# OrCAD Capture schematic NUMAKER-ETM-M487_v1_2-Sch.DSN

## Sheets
1 PAGE04 USB: size B; title: USB; rev: v1.2; note: NuMaker-ETM-M487
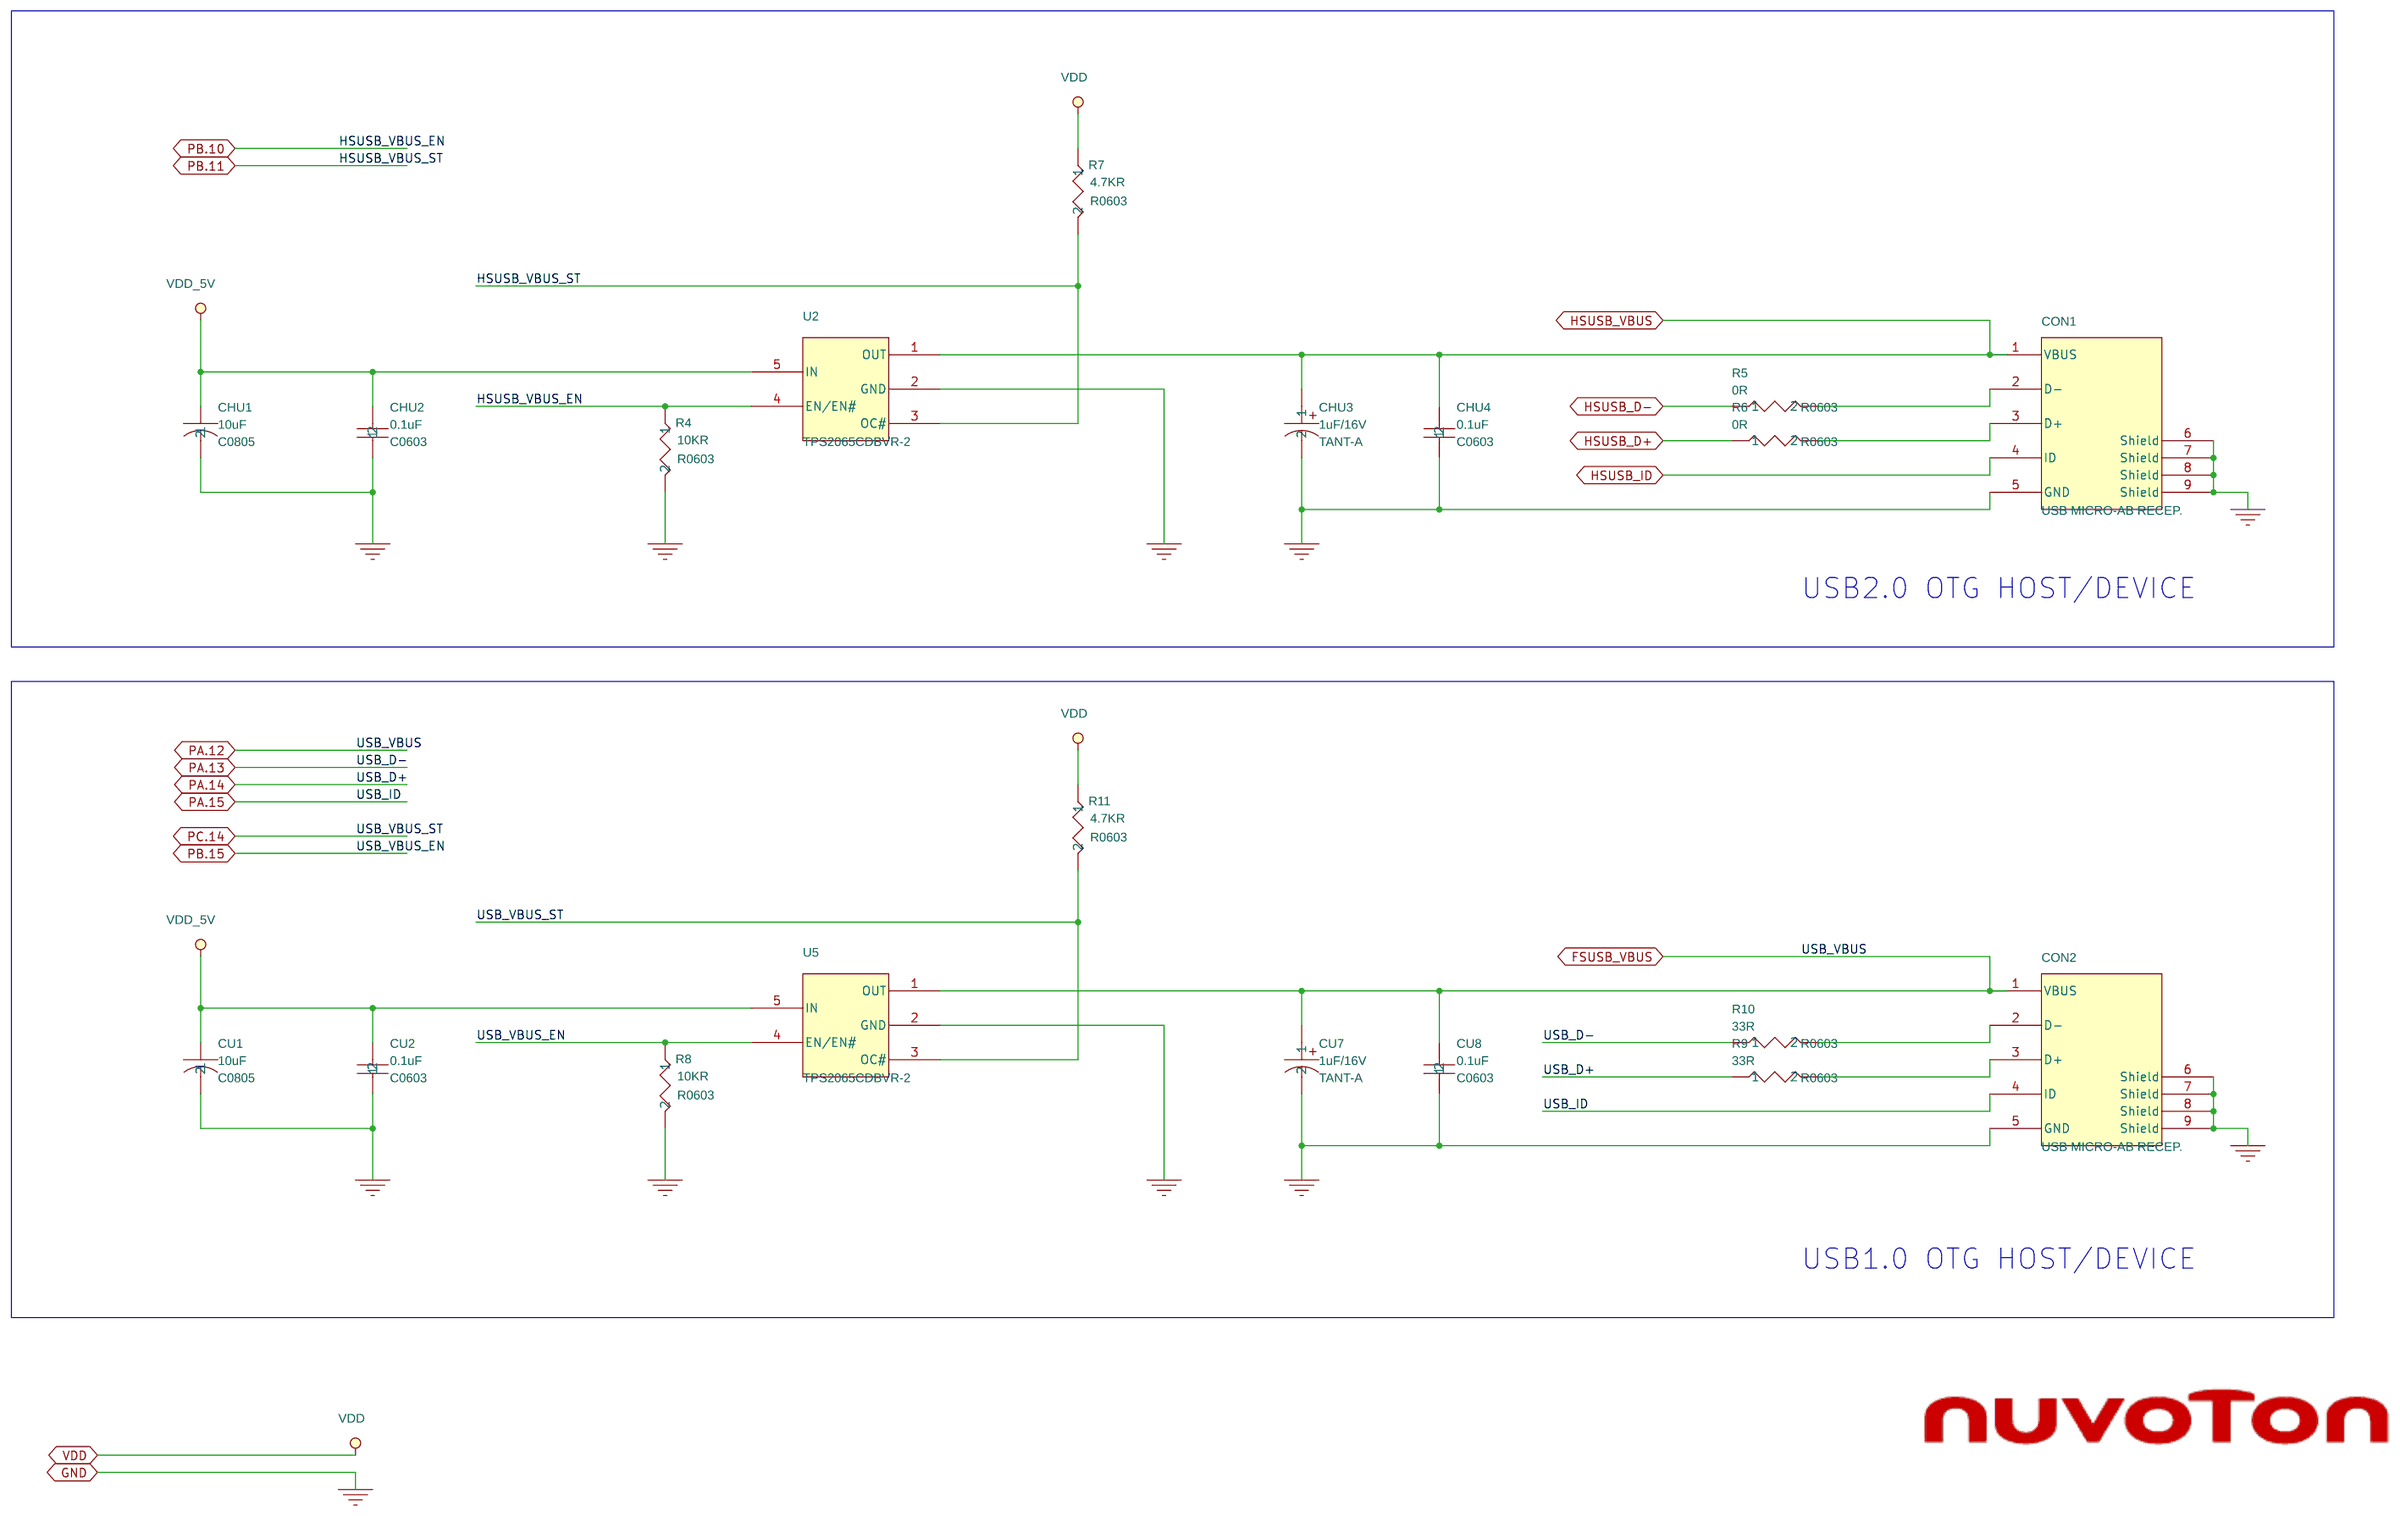
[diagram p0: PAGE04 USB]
2 PAGE01 Nu-Link-Me V3.0: size B; title: Nu-Link-Me v3.0
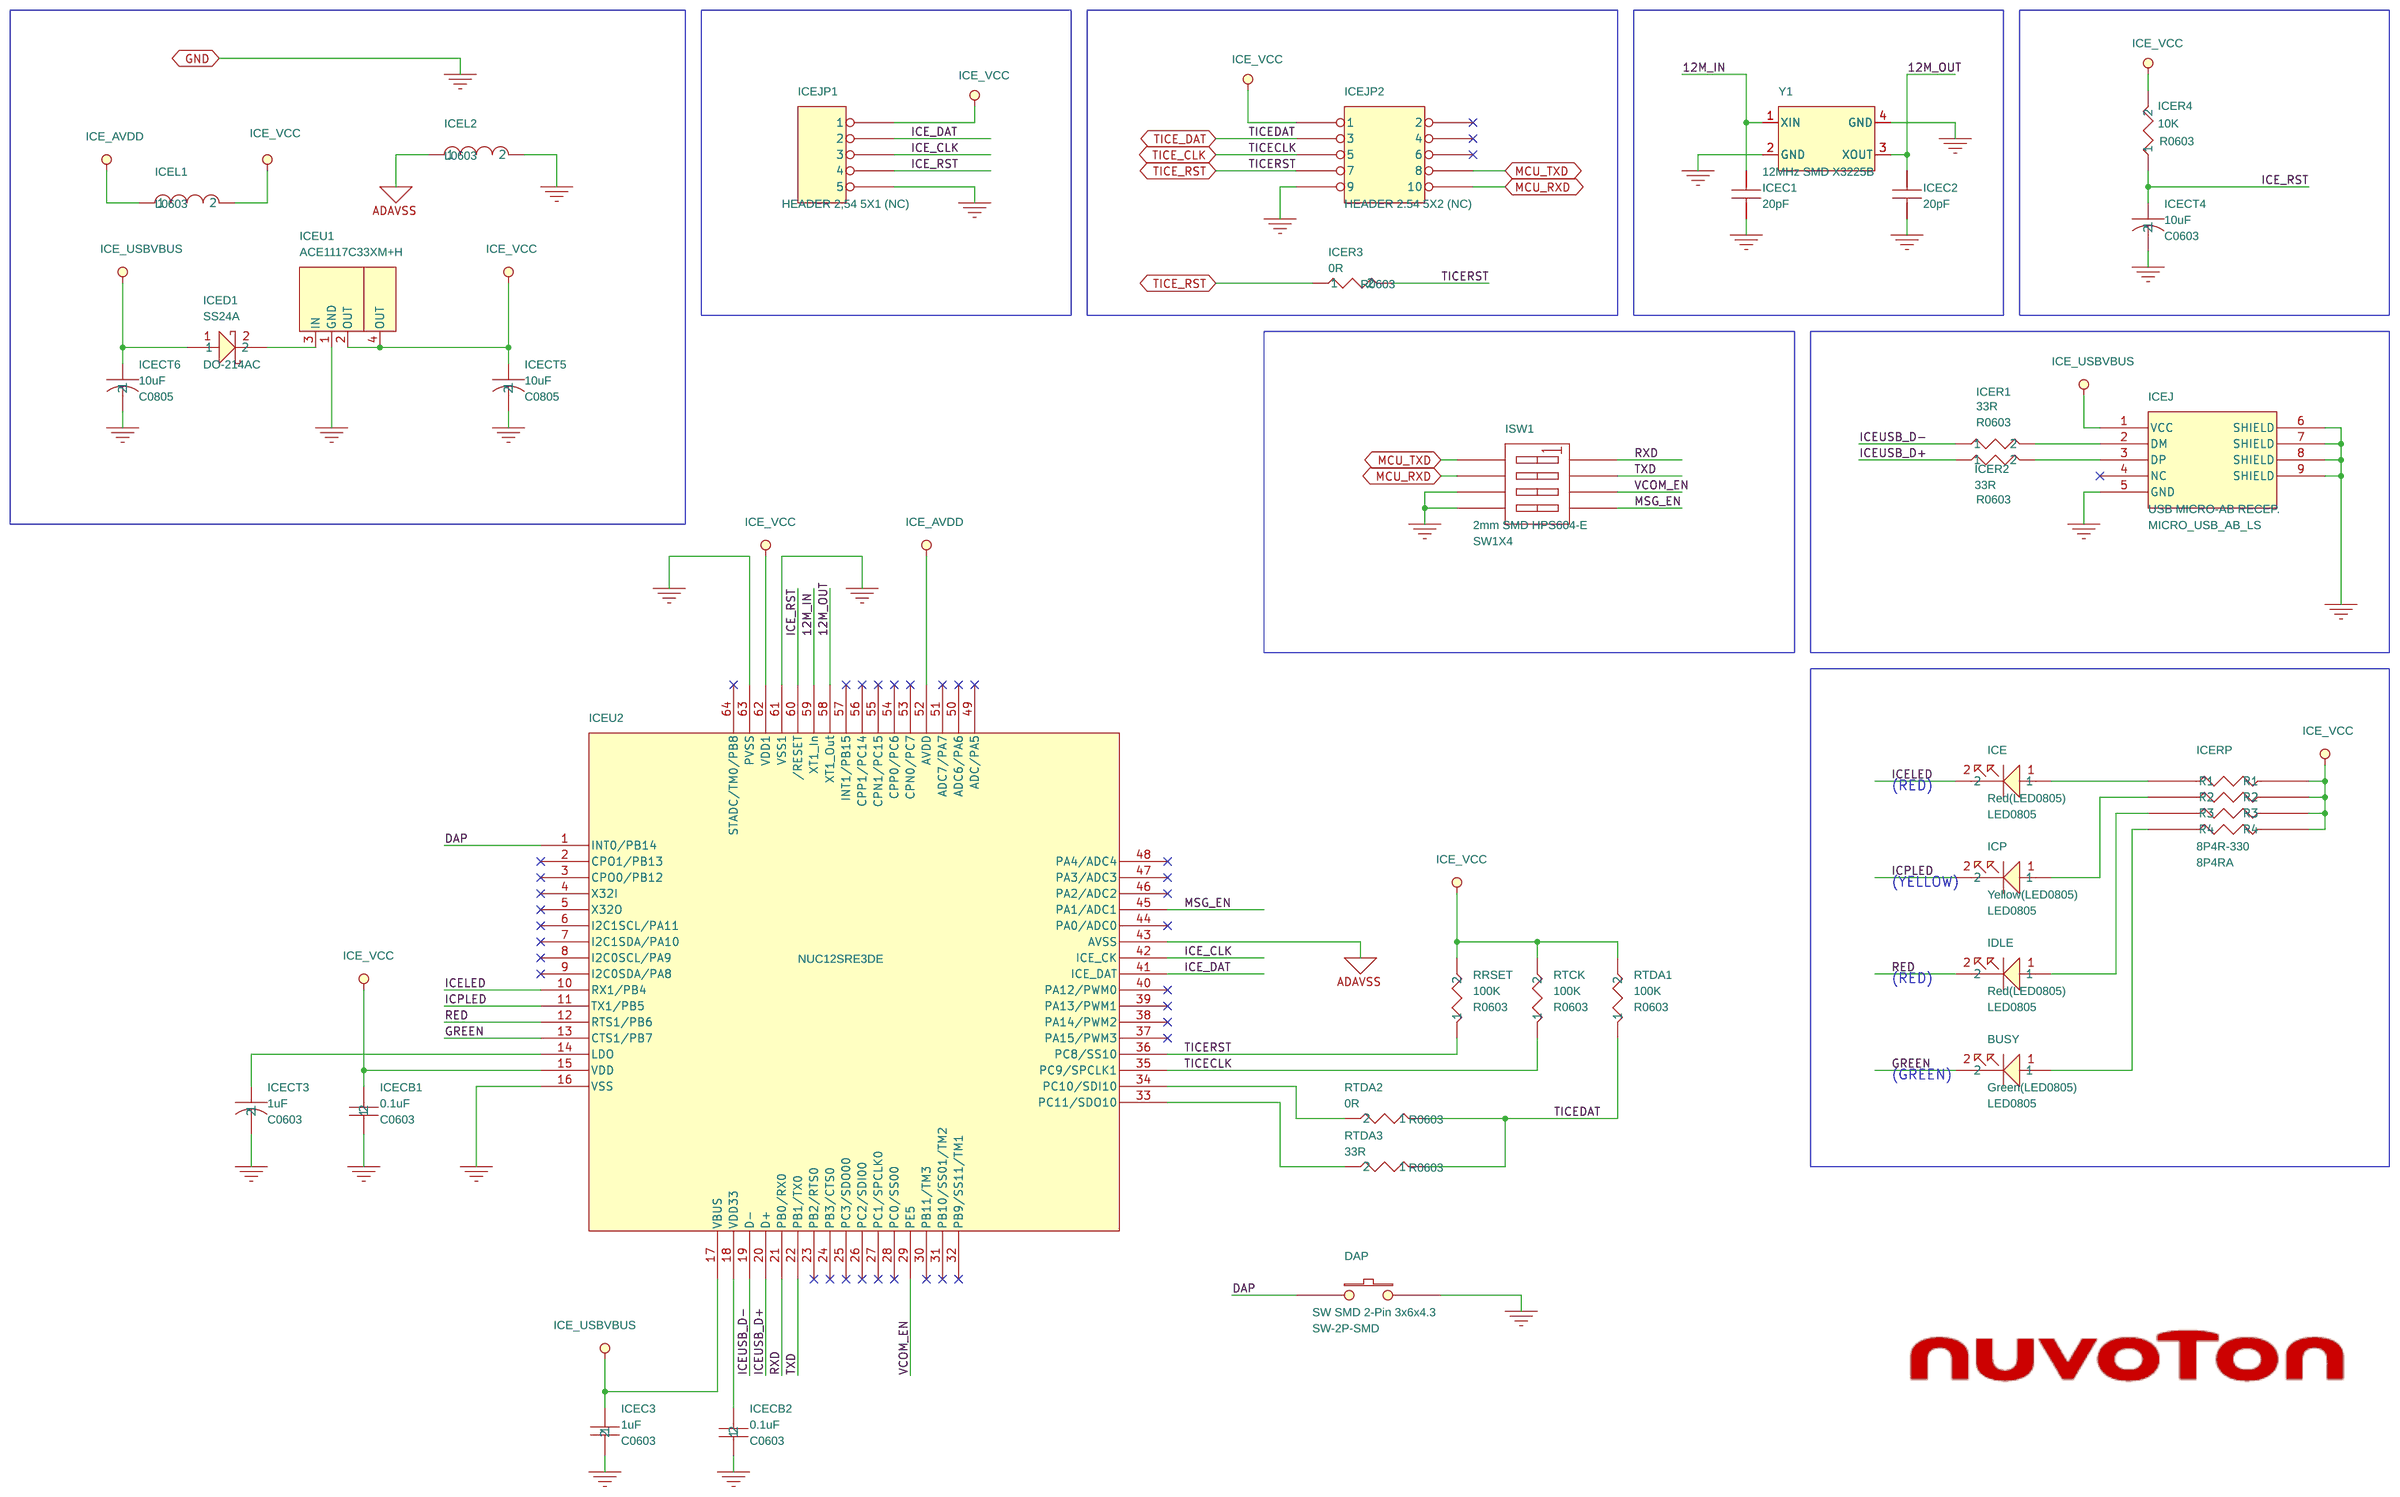
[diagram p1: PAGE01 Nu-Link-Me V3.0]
3 PAGE00 Power: size A; title: Power
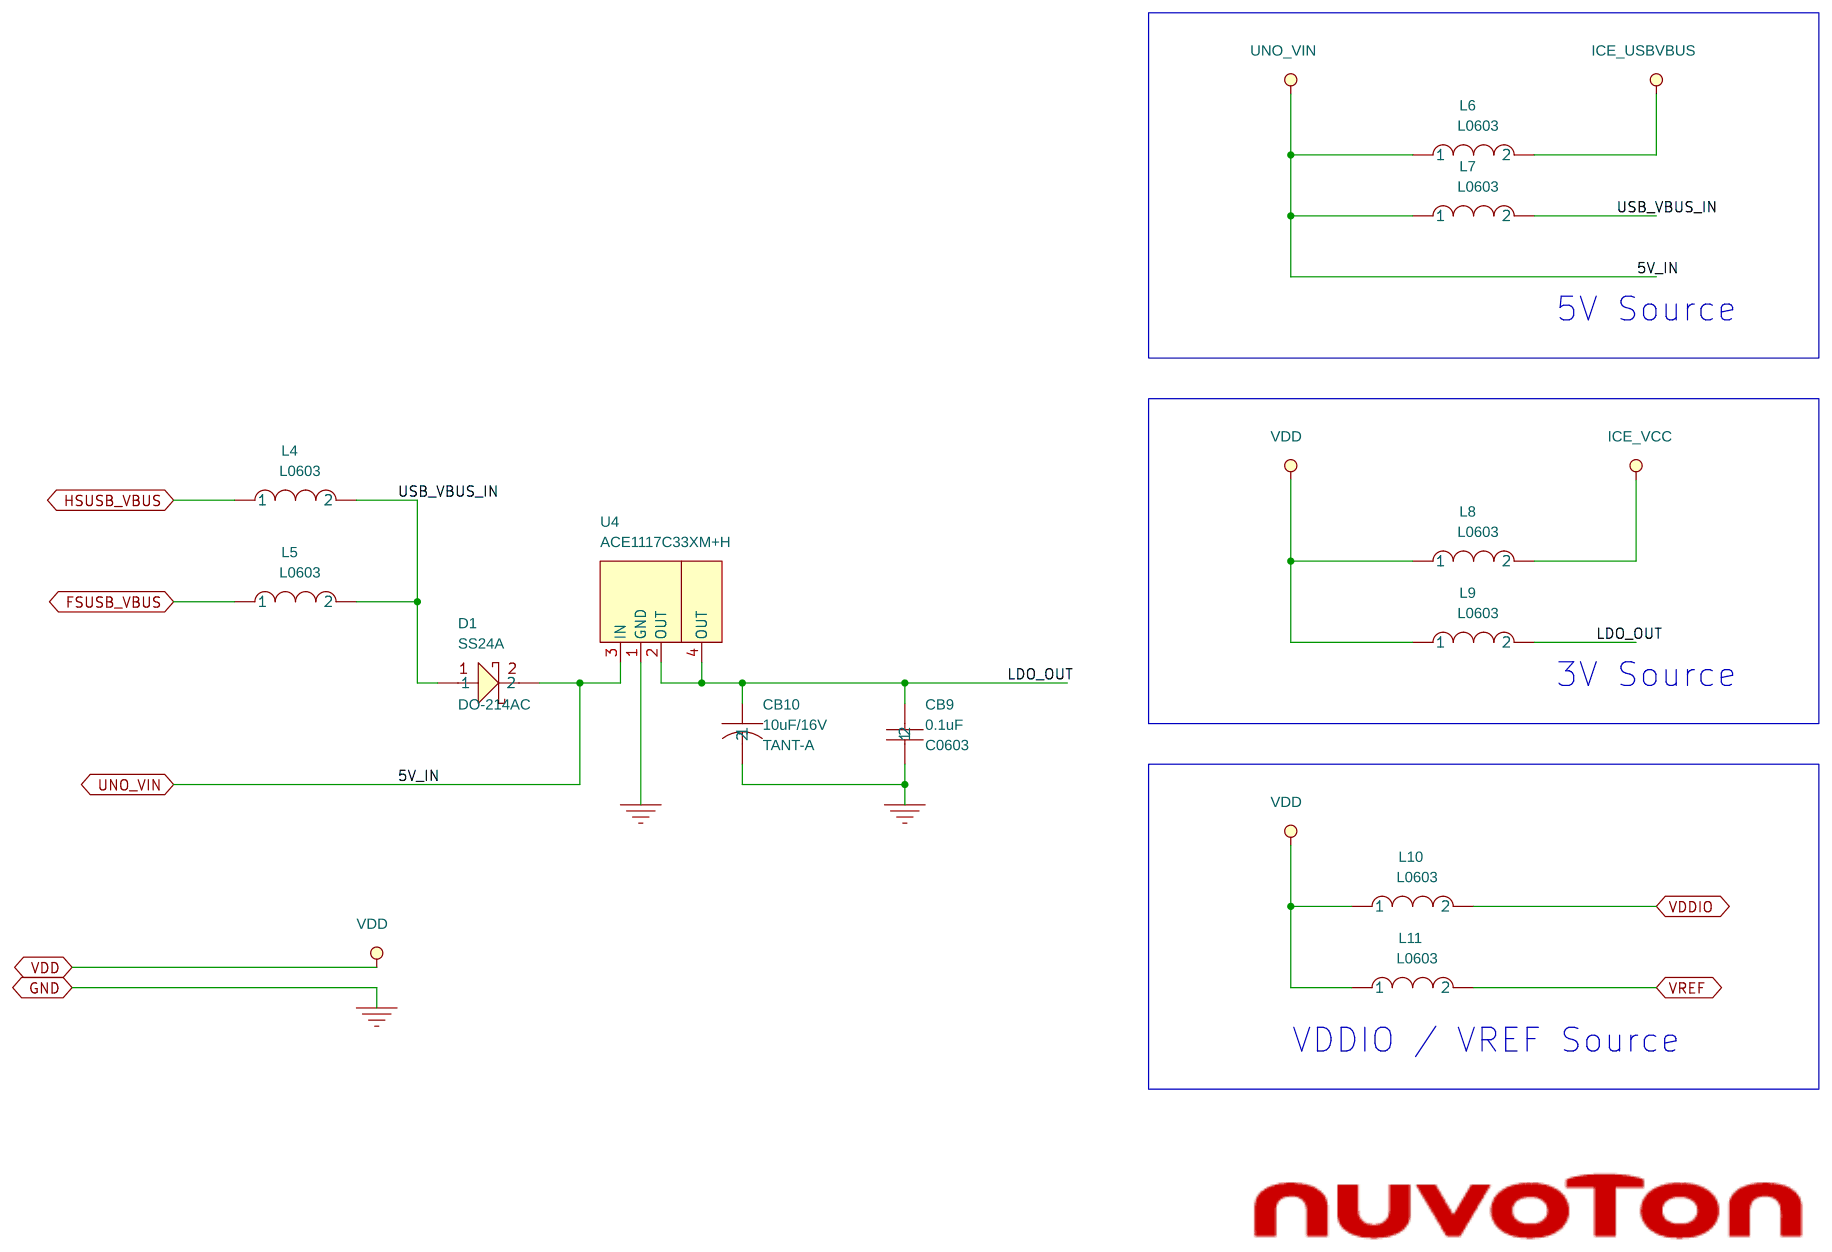
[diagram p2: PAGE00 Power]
4 PAGE03 Ext. Connector: size A; title: Ext. Connector
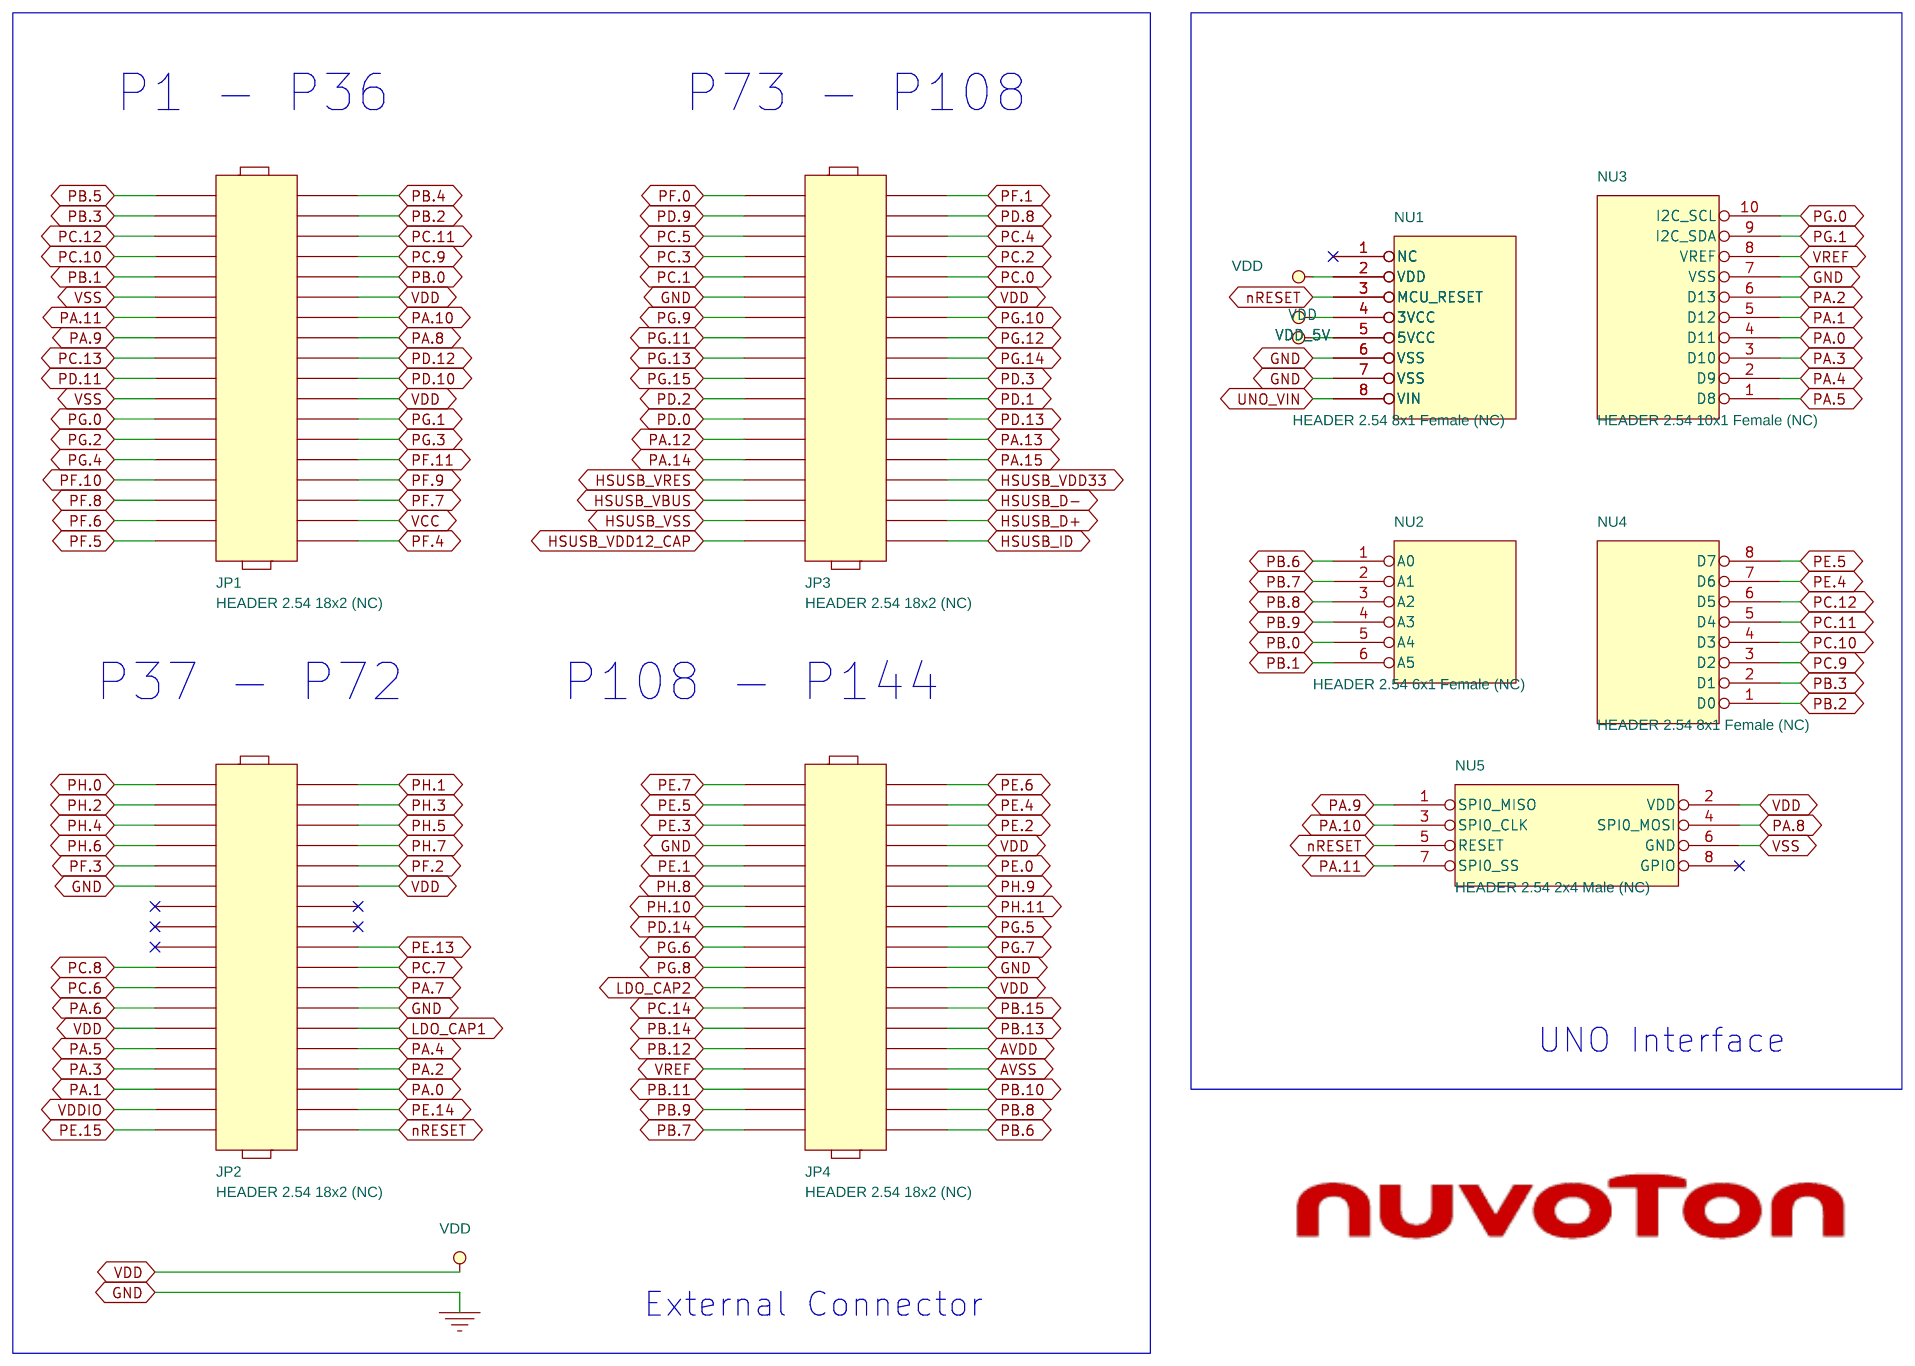
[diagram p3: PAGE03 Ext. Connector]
5 PAGE02 M487JIDAE: size C; title: M487JIDAE MCU
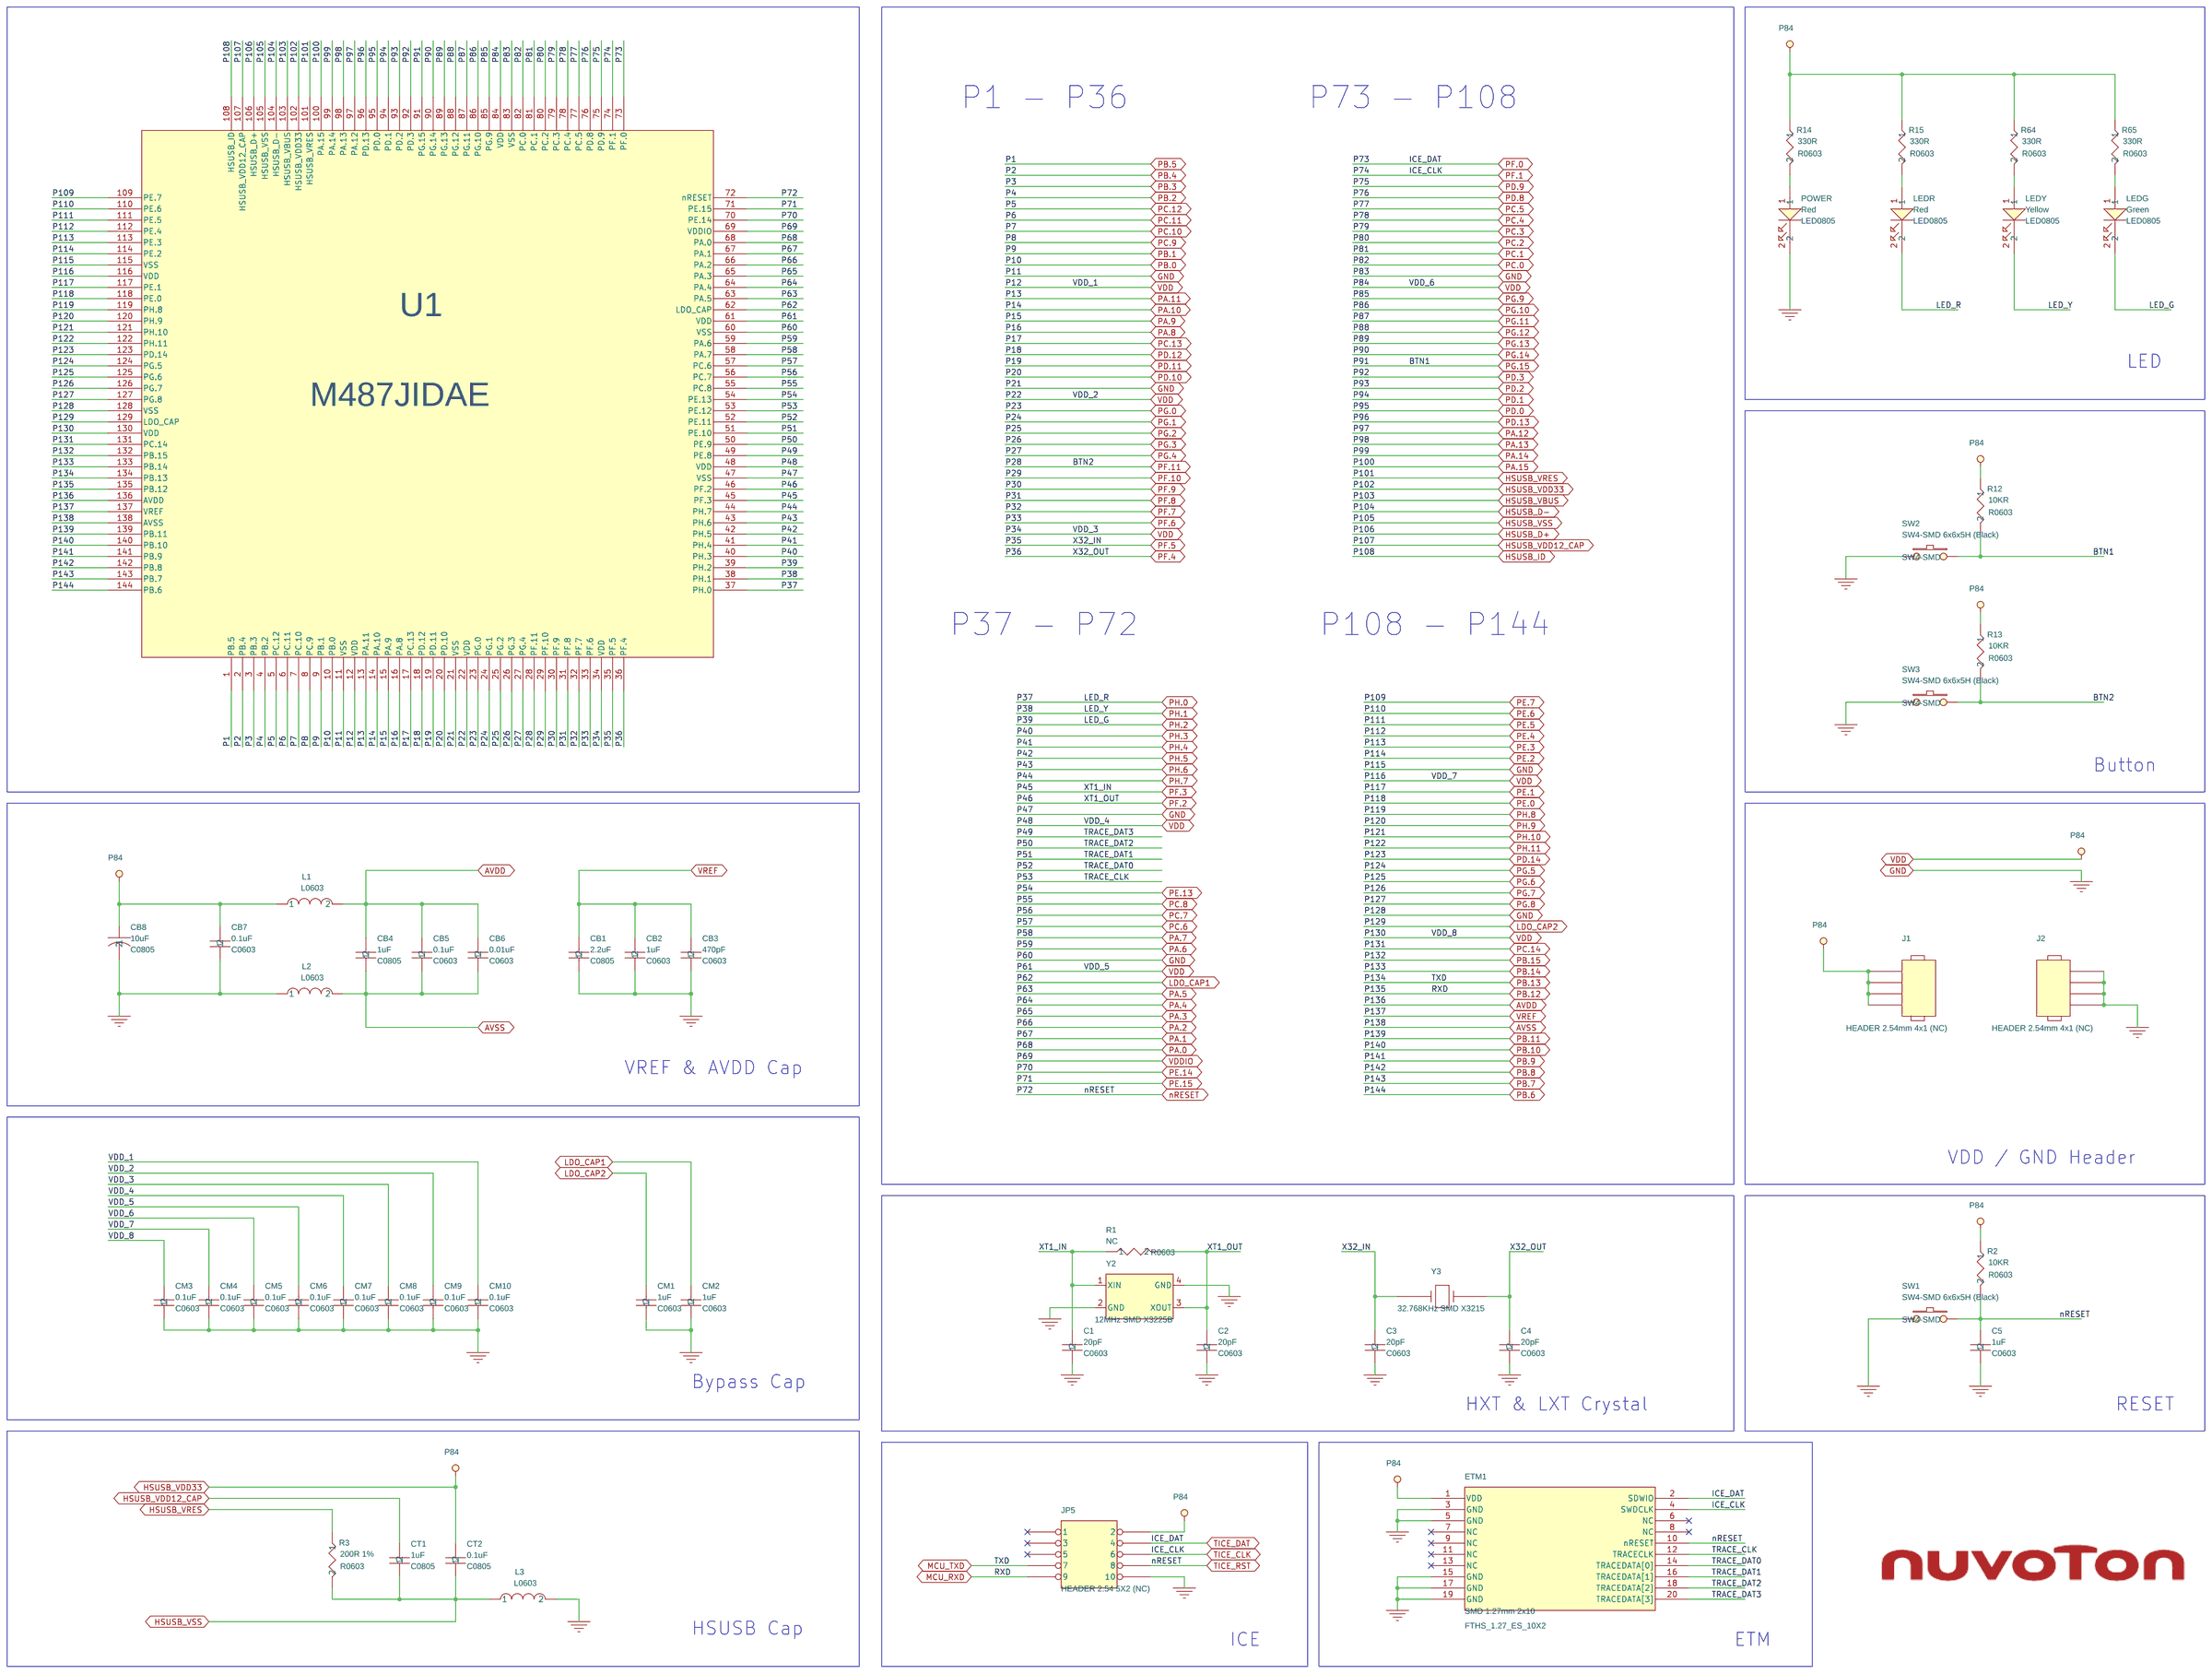
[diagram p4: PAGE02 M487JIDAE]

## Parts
sheet PAGE00 Power
CB9  0.1uF  [C0603]
CB10  10uF/16V  [TANT-A]
D1  SS24A  [DO-214AC]
L4  FERRITE BEAD  [L0603]
L5  FERRITE BEAD  [L0603]
L6  FERRITE BEAD  [L0603]
L7  FERRITE BEAD  [L0603]
L8  FERRITE BEAD  [L0603]
L9  FERRITE BEAD  [L0603]
L10  FERRITE BEAD  [L0603]
L11  FERRITE BEAD  [L0603]
U4  ACE1117C33XM+H  [SOT-223-1]
sheet PAGE01 Nu-Link-Me V3.0
BUSY  Green(LED0805)  [LED0805]
DAP  SW SMD 2-Pin 3x6x4.3  [SW-2P-SMD]
ICE  Red(LED0805)  [LED0805]
ICEC1  20pF  [C0603]
ICEC2  20pF  [C0603]
ICEC3  1uF  [C0603]
ICECB1  0.1uF  [C0603]
ICECB2  0.1uF  [C0603]
ICECT3  1uF  [C0603]
ICECT4  10uF  [C0603]
ICECT5  10uF  [C0805]
ICECT6  10uF  [C0805]
ICED1  SS24A  [DO-214AC]
ICEJ  USB MICRO-AB RECEP.  [MICRO_USB_AB_LS]
ICEJP1  HEADER 2,54 5X1 (NC)  [HEADER5x1]
ICEJP2  HEADER 2.54 5X2 (NC)  [HEADER5X2]
ICEL1  FERRITE BEAD  [L0603]
ICEL2  FERRITE BEAD  [L0603]
ICER1  33R  [R0603]
ICER2  33R  [R0603]
ICER3  0R  [R0603]
ICER4  10K  [R0603]
ICERP  8P4R-330  [8P4RA]
ICEU1  ACE1117C33XM+H  [SOT-223-1]
ICEU2  NUC12SRE3DE  [NCU120_LQFP_64]
ICP  Yellow(LED0805)  [LED0805]
IDLE  Red(LED0805)  [LED0805]
ISW1  2mm SMD HPS604-E  [SW1X4]
RRSET  100K  [R0603]
RTCK  100K  [R0603]
RTDA1  100K  [R0603]
RTDA2  0R  [R0603]
RTDA3  33R  [R0603]
Y1  12MHz SMD X3225B  [XRGBBCNANF-27M]
sheet PAGE02 M487JIDAE
C1  20pF  [C0603]
C2  20pF  [C0603]
C3  20pF  [C0603]
C4  20pF  [C0603]
C5  1uF  [C0603]
CB1  2.2uF  [C0805]
CB2  1uF  [C0603]
CB3  470pF  [C0603]
CB4  1uF  [C0805]
CB5  0.1uF  [C0603]
CB6  0.01uF  [C0603]
CB7  0.1uF  [C0603]
CB8  10uF  [C0805]
CM1  1uF  [C0603]
CM2  1uF  [C0603]
CM3  0.1uF  [C0603]
CM4  0.1uF  [C0603]
CM5  0.1uF  [C0603]
CM6  0.1uF  [C0603]
CM7  0.1uF  [C0603]
CM8  0.1uF  [C0603]
CM9  0.1uF  [C0603]
CM10  0.1uF  [C0603]
CT1  1uF  [C0805]
CT2  0.1uF  [C0805]
ETM1  SMD 1.27mm 2x10  [FTHS_1.27_ES_10X2]
J1  HEADER 2.54mm 4x1 (NC)  [HEADER1x4]
J2  HEADER 2.54mm 4x1 (NC)  [HEADER1x4]
JP5  HEADER 2.54 5X2 (NC)  [HEADER5X2]
L1  FERRITE BEAD  [L0603]
L2  FERRITE BEAD  [L0603]
L3  FERRITE BEAD  [L0603]
LEDG  Green  [LED0805]
LEDR  Red  [LED0805]
LEDY  Yellow  [LED0805]
POWER  Red  [LED0805]
R1  NC  [R0603]
R2  10KR  [R0603]
R3  200R 1%  [R0603]
R12  10KR  [R0603]
R13  10KR  [R0603]
R14  330R  [R0603]
R15  330R  [R0603]
R64  330R  [R0603]
R65  330R  [R0603]
SW1  SW4-SMD 6x6x5H (Black)  [SW4-SMD]
SW2  SW4-SMD 6x6x5H (Black)  [SW4-SMD]
SW3  SW4-SMD 6x6x5H (Black)  [SW4-SMD]
U1  M487JIDAE  [LQFP144]
Y2  12MHz SMD X3225B  [XRGBBCNANF-27M]
Y3  32.768KHz SMD X3215  [9HT9]
sheet PAGE03 Ext. Connector
JP1  HEADER 2.54 18x2 (NC)  [HEADER18X2]
JP2  HEADER 2.54 18x2 (NC)  [HEADER18X2]
JP3  HEADER 2.54 18x2 (NC)  [HEADER18X2]
JP4  HEADER 2.54 18x2 (NC)  [HEADER18X2]
NU1  HEADER 2.54 8x1 Female (NC)  [SIP-8P]
NU2  HEADER 2.54 6x1 Female (NC)  [SIP-6P]
NU3  HEADER 2.54 10x1 Female (NC)  [SIP-10P]
NU4  HEADER 2.54 8x1 Female (NC)  [SIP-8P]
NU5  HEADER 2.54 2x4 Male (NC)  [HEADER4X2]
sheet PAGE04 USB
CHU1  10uF  [C0805]
CHU2  0.1uF  [C0603]
CHU3  1uF/16V  [TANT-A]
CHU4  0.1uF  [C0603]
CON1  USB MICRO-AB RECEP.  [MICRO_USB_AB_LS]
CON2  USB MICRO-AB RECEP.  [MICRO_USB_AB_LS]
CU1  10uF  [C0805]
CU2  0.1uF  [C0603]
CU7  1uF/16V  [TANT-A]
CU8  0.1uF  [C0603]
R4  10KR  [R0603]
R5  0R  [R0603]
R6  0R  [R0603]
R7  4.7KR  [R0603]
R8  10KR  [R0603]
R9  33R  [R0603]
R10  33R  [R0603]
R11  4.7KR  [R0603]
U2  TPS2065CDBVR-2  [SOT23-5]
U5  TPS2065CDBVR-2  [SOT23-5]

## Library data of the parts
CB9 CHU4 CT2 ICECB2 = CAP-C: Package: 0603
CB8 CB10 CHU1 = CAP: Package: TANT-R
D1 ICED1 = DIODE_SCHOTTKY_6: Package: SOD-1231; Vendor: ROHM
L4 = INDUCTOR_3
L5 = INDUCTOR_7
L6 = INDUCTOR_6
L7 = INDUCTOR_5
L1 L8 = INDUCTOR_2
ICEL1 L2 L9 = INDUCTOR_1
ICEL2 L3 L10 = INDUCTOR
L11 = INDUCTOR_4
ICEU1 U4 = TO-247_Regulator_10
BUSY LEDR = LED_0: Package: KP-2012; Vendor: Kingbright
DAP = SW_PUSHBUTTON
ICE LEDG = LED_0_1: Package: KP-2012; Vendor: Kingbright
ICEC1 ICEC2 = CAP_NP
C4 CHU2 ICEC3 = CAP-C_2: Package: 0603
C3 CU2 ICECB1 = CAP-C_1: Package: 0603
ICECT3 = CAP_3: Package: 0603
ICECT4 = CAP_1: Package: 0603
ICECT5 = CAP_2: Package: 0603
ICECT6 = CAP: Package: 0603
ICEJ = 4X1_HEADER_5
ICEJP1 = HEADER_5
ICEJP2 JP5 = HEADER_5X2
ICER1 R3 R5 = R_0_5: Package: 0603
ICER2 R6 R13 = R_0: Package: 0603
ICER3 R11 R12 = R_0_2: Package: 0603
ICER4 R10 R64 = R_0_7: Package: 0603
ICERP = R-PACK8_0
ICEU2 = NCU120_LQFP_64
ICP POWER = LED_0_3: Package: KP-2012; Vendor: Kingbright
IDLE LEDY = LED_0_2: Package: KP-2012; Vendor: Kingbright
ISW1 = SW_DIP-4_SM
R8 R65 RRSET = R_0_6: Package: 0603
R15 RTCK = R_0_8: Package: 0603
R2 R7 RTDA1 = R_0_1: Package: 0603
R9 R14 RTDA2 = R_0_4: Package: 0603
R1 R4 RTDA3 = R_0_3: Package: 0603
Y1 Y2 = Crystal_SMD_2
C1 = CAP-C_7: Package: 0603
C2 = CAP-C_14: Package: 0603
C5 = CAP-C_5: Package: 0603
CB1 = CAP-C_16: Package: 0603
CB2 = CAP-C_18: Package: 0603
CB3 = CAP-C_20: Package: 0603
CB4 = CAP-C_11: Package: 0603
CB5 = CAP-C_13: Package: 0603
CB6 = CAP-C_15: Package: 0603
CB7 = CAP-C_23: Package: 0603
CM1 = CAP-C_22: Package: 0603
CM2 = CAP-C_9: Package: 0603
CM3 = CAP-C_12: Package: 0603
CM4 = CAP-C_21: Package: 0603
CM5 = CAP-C_4: Package: 0603
CM6 = CAP-C_6: Package: 0603
CM7 = CAP-C_8: Package: 0603
CM8 = CAP-C_17: Package: 0603
CM9 CU8 = CAP-C_3: Package: 0603
CM10 = CAP-C_10: Package: 0603
CT1 = CAP-C_19: Package: 0603
ETM1 = ETM_Interface_1
J1 J2 = HEADER_4
SW1-SW3 = SW_PUSHBUTTON_v2: Package: DIP PUSH BOTTOM
U1 = M487_LQFP144_4
Y3 = MA306_SM_1
JP1-JP4 = HEADER_18X2
NU1 = POWER_CONNECT_0
NU2 = ADC_CONNECT_0
NU3 = PWM1_CONNECT_1
NU4 = PWM0_CONNECT_0
NU5 = NuEdu_NU7_0
CHU3 = CAP-T: Package: TANT-R
CON1 CON2 = USB_type_B_mini_connector
CU1 = CAP_1: Package: TANT-R
CU7 = CAP-T_1: Package: TANT-R
U2 U5 = NCT3520U

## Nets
AVDD: CB4.2 CB5.2 CB6.2 JP4.28 L1.2 U1.136(AVDD)
AVSS: CB4.1 CB5.1 CB6.1 JP4.30 L2.2 U1.138(AVSS)
GND: C1.1 C2.1 C3.1 C4.1 C5.1 CB1.1 CB2.1 CB3.1 CB7.1 CB8.2 CB9.1 CB10.2 CHU1.2 CHU2.1 CHU3.2 CHU4.1 CM1.1 CM2.1 CM3.1 CM4.1 CM5.1 CM6.1 CM7.1 CM8.1 CM9.1 CM10.1 CON1.5(GND) CON1.6(Shield) CON1.7(Shield) CON1.8(Shield) CON1.9(Shield) CON2.5(GND) CON2.6(Shield) CON2.7(Shield) CON2.8(Shield) CON2.9(Shield) CU1.2 CU2.1 CU7.2 CU8.1 DAP.2 ETM1.3(GND) ETM1.5(GND) ETM1.15(GND) ETM1.17(GND) ETM1.19(GND) ICEC1.2 ICEC2.2 ICEC3.2 ICECB1.1 ICECB2.1 ICECT3.2 ICECT4.2 ICECT5.2 ICECT6.2 ICEJ.5(GND) ICEJ.6(SHIELD) ICEJ.7(SHIELD) ICEJ.8(SHIELD) ICEJ.9(SHIELD) ICEJP1.5 ICEJP2.9 ICEL2.2 ICEU1.1(GND) ICEU2.16(VSS) ICEU2.61(VSS1) ICEU2.63(PVSS) ISW1.3(A3) ISW1.4(A4) J2.1 J2.2 J2.3 J2.4 JP2.11 JP2.24 JP3.11 JP4.7 JP4.20 JP5.10 L2.1 L3.2 NU1.6(VSS) NU1.7(VSS) NU3.7(VSS) POWER.2 R4.2 R8.2 SW1.1 SW2.1 SW3.1 U1.11(VSS) U1.21(VSS) U1.47(VSS) U1.60(VSS) U1.83(VSS) U1.115(VSS) U1.128(VSS) U2.2(GND) U4.1(GND) U5.2(GND) Y1.2(GND) Y1.4(GND) Y2.2(GND) Y2.4(GND)
VDD_5V: CHU1.1 CHU2.2 CU1.1 CU2.2 D1.2 L6.1 L7.1 NU1.5(5VCC) NU1.8(VIN) U2.5(IN) U4.3(IN) U5.5(IN)
VDDIO: JP2.33 L10.2 U1.69(VDDIO)
VSS: JP1.11 JP1.21 NU5.6(GND)
12M_IN: ICEC1.1 ICEU2.59(XT1_In) Y1.1(XIN)
12M_OUT: ICEC2.1 ICEU2.58(XT1_Out) Y1.3(XOUT)
DAP: DAP.1 ICEU2.1(INT0/PB14)
FSUSB_VBUS: CON2.1(VBUS) CU7.1 CU8.2 JP3.25 L5.1 U1.97(PA.12) U5.1(OUT)
GREEN: BUSY.2 ICEU2.13(CTS1/PB7)
HSUSB_D+: JP3.34 R6.1 U1.106(HSUSB_D+)
HSUSB_D-: JP3.32 R5.1 U1.104(HSUSB_D-)
HSUSB_ID: CON1.4(ID) JP3.36 U1.108(HSUSB_ID)
HSUSB_VBUS: CHU3.1 CHU4.2 CON1.1(VBUS) JP3.31 L4.1 U1.103(HSUSB_VBUS) U2.1(OUT)
HSUSB_VDD12_CAP: CT1.2 JP3.35 U1.107(HSUSB_VDD12_CAP)
HSUSB_VDD33: CB7.2 CB8.1 CM3.2 CM4.2 CM5.2 CM6.2 CM7.2 CM8.2 CM9.2 CM10.2 CT2.2 ETM1.1(VDD) J1.1 J1.2 J1.3 J1.4 JP1.12 JP1.22 JP1.34 JP2.12 JP2.25 JP3.12 JP3.30 JP4.8 JP4.22 JP5.2 L1.1 L8.1 L9.1 L10.1 L11.1 NU1.2(VDD) NU1.4(3VCC) NU5.2(VDD) R2.1 R7.1 R11.1 R12.1 R13.1 R14.1 R15.1 R64.1 R65.1 U1.12(VDD) U1.22(VDD) U1.34(VDD) U1.48(VDD) U1.61(VDD) U1.84(VDD) U1.102(HSUSB_VDD33) U1.116(VDD) U1.130(VDD)
HSUSB_VRES: JP3.29 R3.1 U1.101(HSUSB_VRES)
HSUSB_VSS: CT1.1 CT2.1 JP3.33 L3.1 R3.2 U1.105(HSUSB_VSS)
ICE_ADAVSS: ICEL2.1 ICEU2.43(AVSS)
ICE_AVDD: ICEL1.1 ICEU2.52(AVDD)
ICE_CLK: ICEJP1.3 ICEU2.42(ICE_CK)
ICE_DAT: ICEJP1.2 ICEU2.41(ICE_DAT)
ICE_RST: ICECT4.1 ICEJP1.4 ICER4.1 ICEU2.60(/RESET)
ICE_USBVBUS: ICEC3.1 ICECT6.1 ICED1.1 ICEJ.1(VCC) ICEU2.17(VBUS) L6.2
ICE_VCC: ICECB1.2 ICECT5.1 ICEJP1.1 ICEJP2.1 ICEL1.2 ICER4.2 ICERP.2(R1) ICERP.4(R2) ICERP.6(R3) ICERP.8(R4) ICEU1.2(OUT) ICEU1.4(OUT) ICEU2.15(VDD) ICEU2.62(VDD1) L8.2 RRSET.2 RTCK.2 RTDA1.2
ICELED: ICE.2 ICEU2.10(RX1/PB4)
ICEUSB_D+: ICER2.1 ICEU2.20(D+)
ICEUSB_D-: ICER1.1 ICEU2.19(D-)
ICPLED: ICEU2.11(TX1/PB5) ICP.2
LDO_CAP1: CM2.2 JP2.26 U1.62(LDO_CAP)
LDO_CAP2: CM1.2 JP4.21 U1.129(LDO_CAP)
LDO_OUT: CB9.2 CB10.1 L9.2 U4.2(OUT) U4.4(OUT)
MCU_RXD: ICEJP2.10 ISW1.2(A2) JP4.27 JP5.9 U1.135(PB.12)
MCU_TXD: ICEJP2.8 ISW1.1(A1) JP4.26 JP5.7 U1.134(PB.13)
MSG_EN: ICEU2.45(PA1/ADC1) ISW1.5(B4)
P49: ETM1.20(TRACEDATA[3]) U1.49(PE.8)
P50: ETM1.18(TRACEDATA[2]) U1.50(PE.9)
P51: ETM1.16(TRACEDATA[1]) U1.51(PE.10)
P52: ETM1.14(TRACEDATA[0]) U1.52(PE.11)
P53: ETM1.12(TRACECLK) U1.53(PE.12)
PA.0: JP2.32 NU3.4(D11) U1.68(PA.0)
PA.1: JP2.31 NU3.5(D12) U1.67(PA.1)
PA.2: JP2.30 NU3.6(D13) U1.66(PA.2)
PA.3: JP2.29 NU3.3(D10) U1.65(PA.3)
PA.4: JP2.28 NU3.2(D9) U1.64(PA.4)
PA.5: JP2.27 NU3.1(D8) U1.63(PA.5)
PA.6: JP2.23 U1.59(PA.6)
PA.7: JP2.22 U1.58(PA.7)
PA.8: JP1.16 NU5.4(SPI0_MOSI) U1.16(PA.8)
PA.9: JP1.15 NU5.1(SPI0_MISO) U1.15(PA.9)
PA.10: JP1.14 NU5.3(SPI0_CLK) U1.14(PA.10)
PA.11: JP1.13 NU5.7(SPI0_SS) U1.13(PA.11)
PA.13: JP3.26 R10.1 U1.98(PA.13)
PA.14: JP3.27 R9.1 U1.99(PA.14)
PA.15: CON2.4(ID) JP3.28 U1.100(PA.15)
PB.0: JP1.10 NU2.5(A4) U1.10(PB.0)
PB.1: JP1.9 NU2.6(A5) U1.9(PB.1)
PB.2: JP1.4 NU4.1(D0) U1.4(PB.2)
PB.3: JP1.3 NU4.2(D1) U1.3(PB.3)
PB.4: JP1.2 U1.2(PB.4)
PB.5: JP1.1 U1.1(PB.5)
PB.6: JP4.36 NU2.1(A0) U1.144(PB.6)
PB.7: JP4.35 NU2.2(A1) U1.143(PB.7)
PB.8: JP4.34 NU2.3(A2) U1.142(PB.8)
PB.9: JP4.33 NU2.4(A3) U1.141(PB.9)
PB.10: JP4.32 R4.1 U1.140(PB.10) U2.4(EN/EN#)
PB.11: JP4.31 R7.2 U1.139(PB.11) U2.3(OC#)
PB.14: JP4.25 U1.133(PB.14)
PB.15: JP4.24 R8.1 U1.132(PB.15) U5.4(EN/EN#)
PC.0: JP3.10 U1.82(PC.0)
PC.1: JP3.9 U1.81(PC.1)
PC.2: JP3.8 U1.80(PC.2)
PC.3: JP3.7 U1.79(PC.3)
PC.4: JP3.6 U1.78(PC.4)
PC.5: JP3.5 U1.77(PC.5)
PC.6: JP2.21 U1.57(PC.6)
PC.7: JP2.20 U1.56(PC.7)
PC.8: JP2.19 U1.55(PC.8)
PC.9: JP1.8 NU4.3(D2) U1.8(PC.9)
PC.10: JP1.7 NU4.4(D3) U1.7(PC.10)
PC.11: JP1.6 NU4.5(D4) U1.6(PC.11)
PC.12: JP1.5 NU4.6(D5) U1.5(PC.12)
PC.13: JP1.17 U1.17(PC.13)
PC.14: JP4.23 R11.2 U1.131(PC.14) U5.3(OC#)
PD.0: JP3.23 U1.95(PD.0)
PD.1: JP3.22 U1.94(PD.1)
PD.2: JP3.21 U1.93(PD.2)
PD.3: JP3.20 U1.92(PD.3)
PD.8: JP3.4 U1.76(PD.8)
PD.9: JP3.3 U1.75(PD.9)
PD.10: JP1.20 U1.20(PD.10)
PD.11: JP1.19 U1.19(PD.11)
PD.12: JP1.18 U1.18(PD.12)
PD.13: JP3.24 U1.96(PD.13)
PD.14: JP4.15 U1.123(PD.14)
PE.0: JP4.10 U1.118(PE.0)
PE.1: JP4.9 U1.117(PE.1)
PE.2: JP4.6 U1.114(PE.2)
PE.3: JP4.5 U1.113(PE.3)
PE.4: JP4.4 NU4.7(D6) U1.112(PE.4)
PE.5: JP4.3 NU4.8(D7) U1.111(PE.5)
PE.6: JP4.2 U1.110(PE.6)
PE.7: JP4.1 U1.109(PE.7)
PE.13: JP2.18 U1.54(PE.13)
PE.14: JP2.34 U1.70(PE.14)
PE.15: JP2.35 U1.71(PE.15)
PF.0: ETM1.2(SDWIO) ICEJP2.3 JP3.1 JP5.4 RTDA1.1 RTDA2.1 RTDA3.1 U1.73(PF.0)
PF.1: ETM1.4(SWDCLK) ICEJP2.5 ICEU2.35(PC9/SPCLK1) JP3.2 JP5.6 RTCK.1 U1.74(PF.1)
PF.2: C2.2 JP2.10 R1.2 U1.46(PF.2) Y2.3(XOUT)
PF.3: C1.2 JP2.9 R1.1 U1.45(PF.3) Y2.1(XIN)
PF.4: C4.2 JP1.36 U1.36(PF.4) Y3.1
PF.5: C3.2 JP1.35 U1.35(PF.5) Y3.2
PF.6: JP1.33 U1.33(PF.6)
PF.7: JP1.32 U1.32(PF.7)
PF.8: JP1.31 U1.31(PF.8)
PF.9: JP1.30 U1.30(PF.9)
PF.10: JP1.29 U1.29(PF.10)
PF.11: JP1.28 R13.2 SW3.2 U1.28(PF.11)
PG.0: JP1.23 NU3.10(I2C_SCL) U1.23(PG.0)
PG.1: JP1.24 NU3.9(I2C_SDA) U1.24(PG.1)
PG.2: JP1.25 U1.25(PG.2)
PG.3: JP1.26 U1.26(PG.3)
PG.4: JP1.27 U1.27(PG.4)
PG.5: JP4.16 U1.124(PG.5)
PG.6: JP4.17 U1.125(PG.6)
PG.7: JP4.18 U1.126(PG.7)
PG.8: JP4.19 U1.127(PG.8)
PG.9: JP3.13 U1.85(PG.9)
PG.10: JP3.14 U1.86(PG.10)
PG.11: JP3.15 U1.87(PG.11)
PG.12: JP3.16 U1.88(PG.12)
PG.13: JP3.17 U1.89(PG.13)
PG.14: JP3.18 U1.90(PG.14)
PG.15: JP3.19 R12.2 SW2.2 U1.91(PG.15)
PH.0: JP2.1 LEDR.2 U1.37(PH.0)
PH.1: JP2.2 LEDY.2 U1.38(PH.1)
PH.2: JP2.3 LEDG.2 U1.39(PH.2)
PH.3: JP2.4 U1.40(PH.3)
PH.4: JP2.5 U1.41(PH.4)
PH.5: JP2.6 U1.42(PH.5)
PH.6: JP2.7 U1.43(PH.6)
PH.7: JP2.8 U1.44(PH.7)
PH.8: JP4.11 U1.119(PH.8)
PH.9: JP4.12 U1.120(PH.9)
PH.10: JP4.13 U1.121(PH.10)
PH.11: JP4.14 U1.122(PH.11)
RED: ICEU2.12(RTS1/PB6) IDLE.2
RXD: ICEU2.21(PB0/RX0) ISW1.8(B1)
TICE_RST: C5.2 ETM1.10(nRESET) ICEJP2.7 ICER3.1 ICER3.2 ICEU2.36(PC8/SS10) JP2.36 JP5.8 NU1.3(MCU_RESET) NU5.5(RESET) R2.2 RRSET.1 SW1.2 U1.72(nRESET)
TXD: ICEU2.22(PB1/TX0) ISW1.7(B2)
USB_VBUS_IN: D1.1 L4.2 L5.2 L7.2
VCOM_EN: ICEU2.29(PE5) ISW1.6(B3)
VREF: CB1.2 CB2.2 CB3.2 JP4.29 L11.2 NU3.8(VREF) U1.137(VREF)
N16779660: ICEJ.2(DM) ICER1.2
N16779663: ICEJ.3(DP) ICER2.2
N16780219: ICECT3.1 ICEU2.14(LDO)
N16780291: ICECB2.2 ICEU2.18(VDD33)
N16780374: ICEU2.34(PC10/SDI10) RTDA2.2
N16780389: ICEU2.33(PC11/SDO10) RTDA3.2
N16781027: BUSY.1 ICERP.7(R4)
N16781042: ICERP.5(R3) IDLE.1
N16781058: ICE.1 ICERP.1(R1)
N16781087: ICERP.3(R2) ICP.1
N16781655: ICED1.2 ICEU1.3(IN)
N16798639: CON1.2(D-) R5.2
N16799113: CON1.3(D+) R6.2
N16801628: CON2.2(D-) R10.2
N16801680: CON2.3(D+) R9.2
N16825237: POWER.1 R14.2
N16825240: LEDR.1 R15.2
N16825243: LEDY.1 R64.2
N16825246: LEDG.1 R65.2

Not connected (* = marked no-connect by the designer): ETM1 6(NC)* 7(NC)* 8(NC)* 9(NC)* 11(NC)* 13(NC)*; ICEJ 4(NC)*; ICEJP2 2* 4* 6*; ICEU2 2(CPO1/PB13)* 3(CPO0/PB12)* 4(X32I)* 5(X32O)* 6(I2C1SCL/PA11)* 7(I2C1SDA/PA10)* 8(I2C0SCL/PA9)* 9(I2C0SDA/PA8)* 23(PB2/RTS0)* 24(PB3/CTS0)* 25(PC3/SDO00)* 26(PC2/SDI00)* 27(PC1/SPCLK0)* 28(PC0/SS00)* 30(PB11/TM3)* 31(PB10/SS01/TM2)* 32(PB9/SS11/TM1)* 37(PA15/PWM3)* 38(PA14/PWM2)* 39(PA13/PWM1)* 40(PA12/PWM0)* 44(PA0/ADC0)* 46(PA2/ADC2)* 47(PA3/ADC3)* 48(PA4/ADC4)* 49(ADC/PA5)* 50(ADC6/PA6)* 51(ADC7/PA7)* 53(CPN0/PC7)* 54(CPP0/PC6)* 55(CPN1/PC15)* 56(CPP1/PC14)* 57(INT1/PB15)* 64(STADC/TM0/PB8)*; JP2 13* 14* 15* 16* 17*; JP5 1* 3* 5*; NU1 1(NC)*; NU5 8(GPIO)*

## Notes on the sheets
sheet 1
- USB2.0 OTG HOST/DEVICE
- USB1.0 OTG HOST/DEVICE
sheet 2
- (RED)
- (YELLOW)
- (RED)
- (GREEN)
sheet 3
- 5V Source
- 3V Source
- VDDIO / VREF Source
sheet 4
- P1 - P36
- P73 - P108
- P37 - P72
- P108 - P144
- UNO Interface
- External Connector
sheet 5
- P1 - P36
- P73 - P108
- LED
- P37 - P72
- P108 - P144
- Button
- VREF & AVDD Cap
- VDD / GND Header
- Bypass Cap
- HXT & LXT Crystal
- RESET
- HSUSB Cap
- ICE
- ETM
